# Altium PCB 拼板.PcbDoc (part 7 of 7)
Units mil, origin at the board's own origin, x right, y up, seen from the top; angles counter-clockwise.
Board outline 3630.03 x 5330.03 mil, 2 copper layers (Top Layer, Bottom Layer); 416 components, 35 nets, 1936 pads, 800 vias.
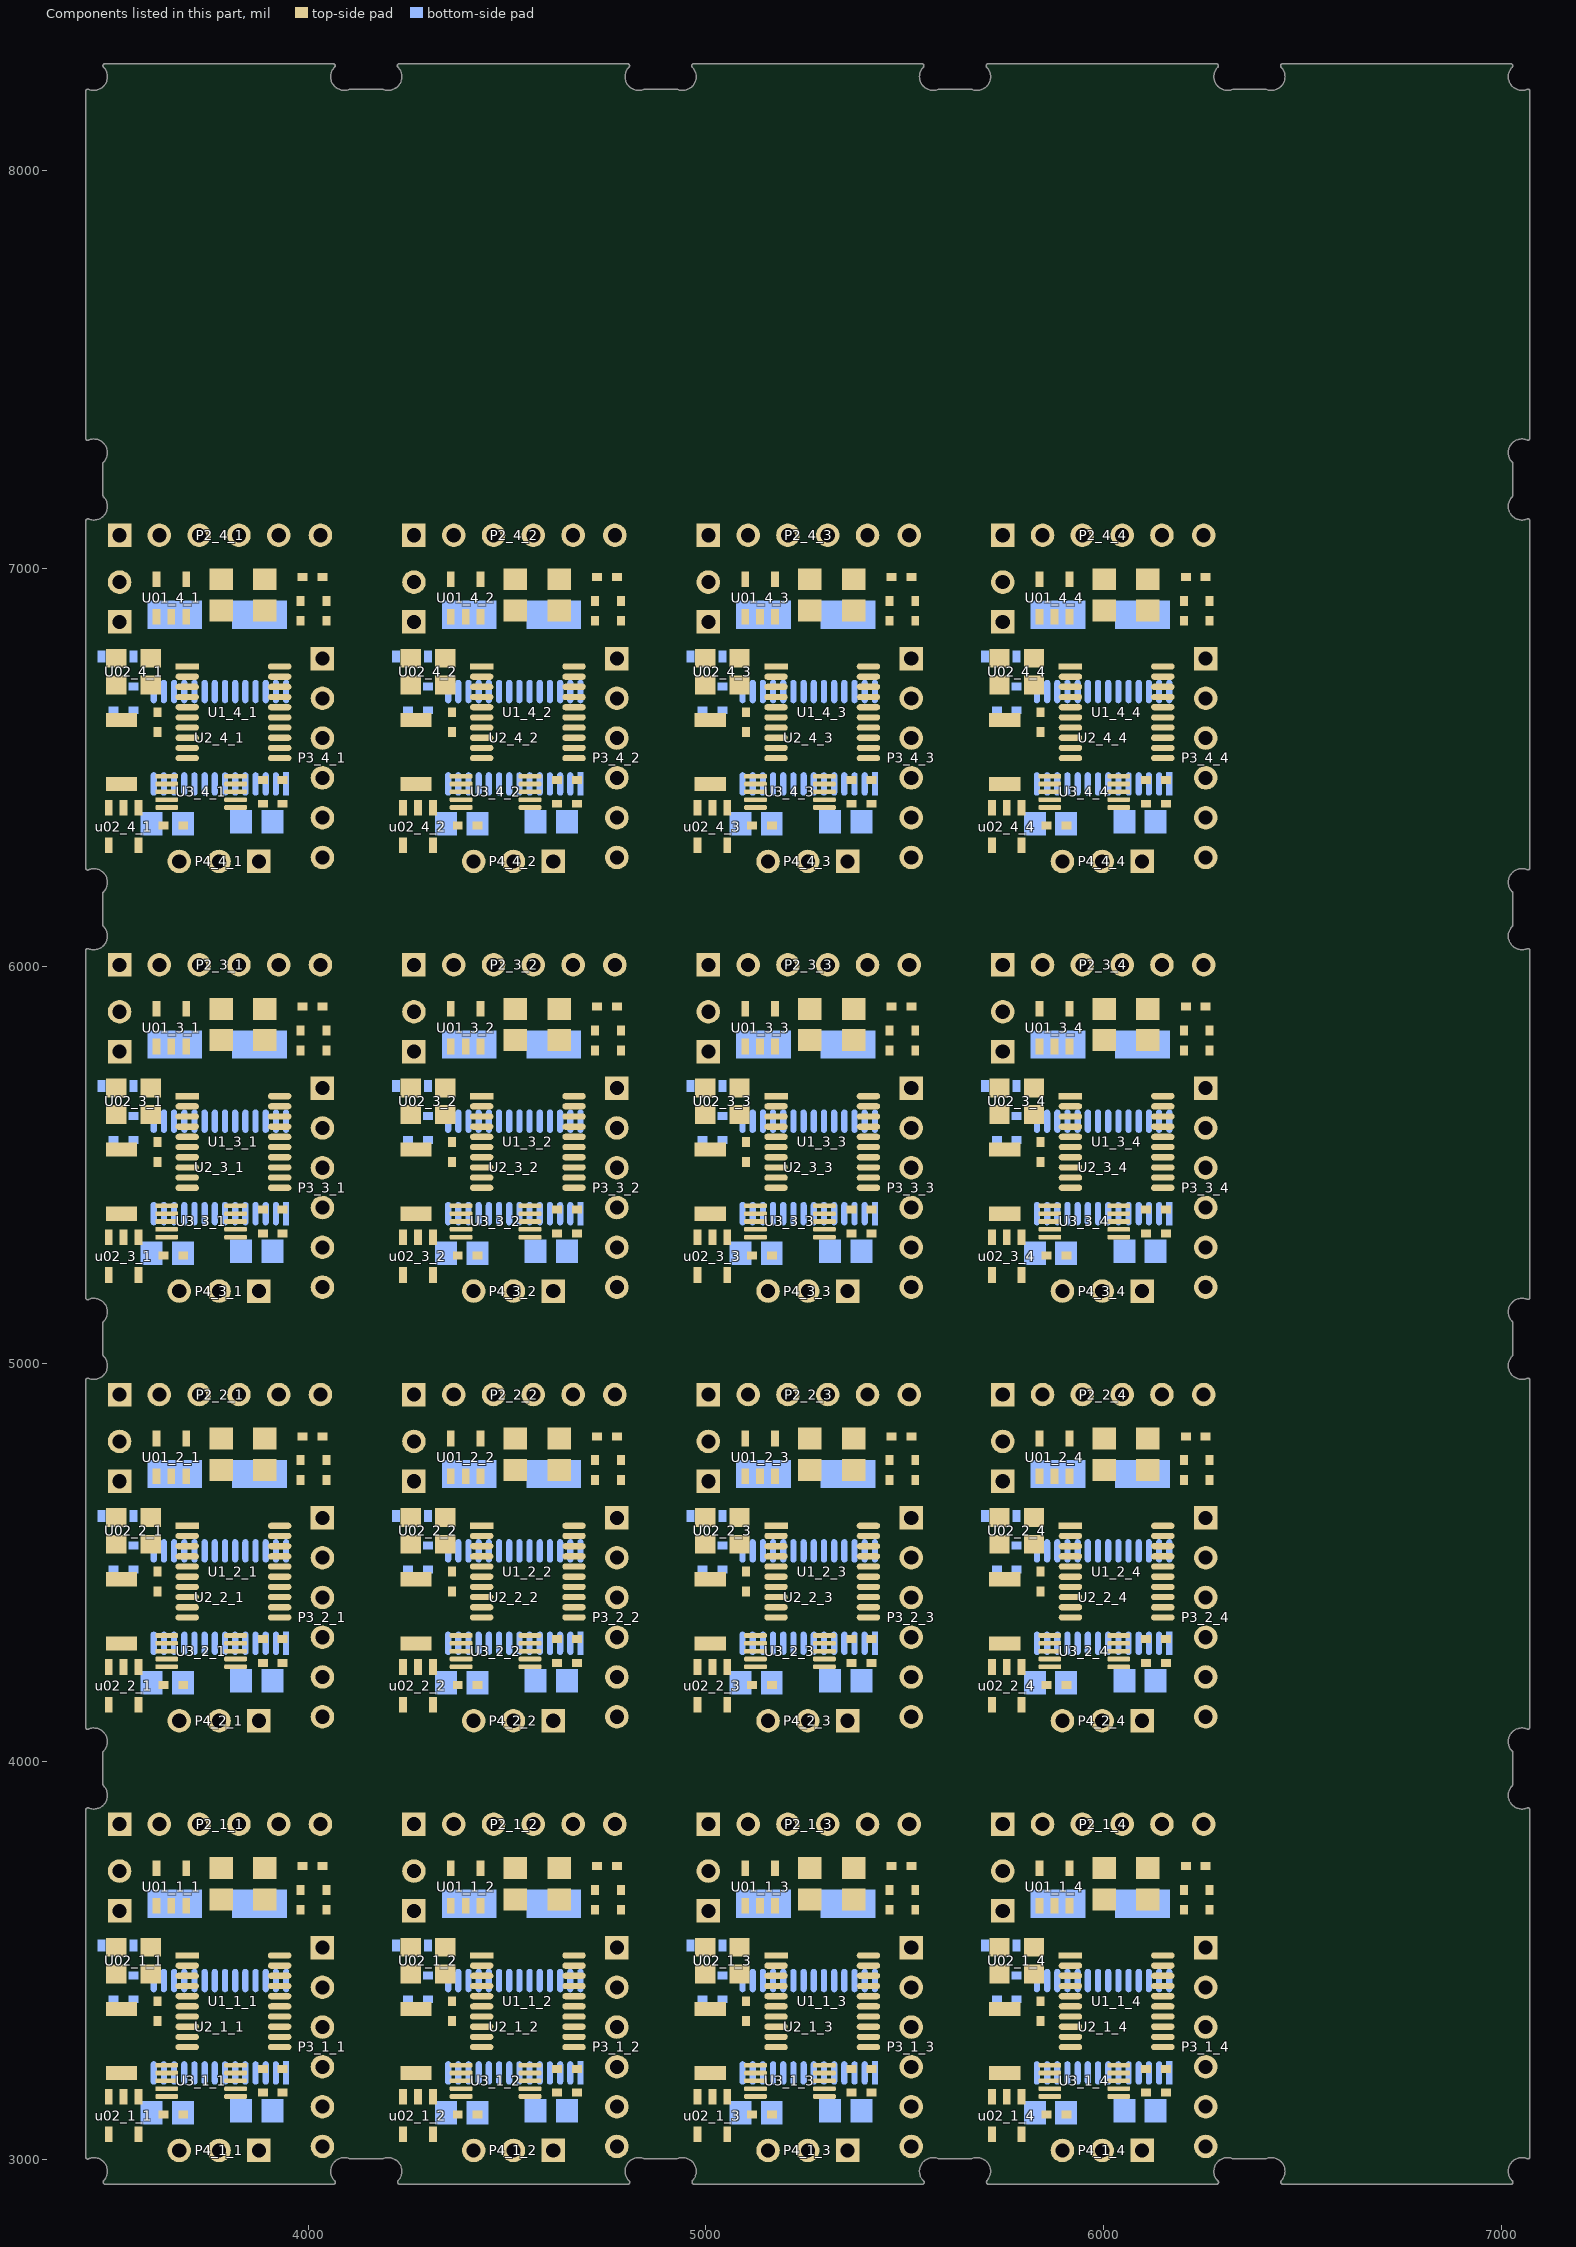
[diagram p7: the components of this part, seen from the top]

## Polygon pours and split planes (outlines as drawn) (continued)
no net on Bottom Layer "Top Layer-No Net1" (solid, pour order 43): 4929.77,3003.01 cw(c4926.07,3006.39) 4921.05,3006.39 4921.05,3879.08 cw(c4926.07,3879.08) 4927.98,3883.71 ccw(c4941.11,3915.46) 4975.46,3915.46 ccw(c4941.11,3915.46) 4965.67,3939.48 ccw(c4941.11,3915.46) 4965.64,3939.51 4965.67,3939.48 cw(c4969.22,3943.02) 4964.21,3943.02 cw(c4969.22,3943.02) 4969.25,3948.04 5542.91,3948.04 cw(c5542.91,3943.02) 5547.93,3943.02 cw(c5542.91,3943.02) 5546.47,3939.49 cw(c5571.03,3915.46) 5546.49,3939.51 5546.47,3939.49 ccw(c5571.03,3915.46) 5584.15,3883.71 cw(c5586.07,3879.08) 5591.08,3879.08 cw(c5586.07,3879.08) 5591.08,3879.08 5591.08,3006.97 cw(c5586.07,3006.97) 5584.15,3002.33 ccw(c5571.03,2970.58) 5545.44,2947.65 cw(c5543.51,2943.02) 5548.53,2943.02 cw(c5543.51,2943.02) 5543.51,2938.01 5537.29,2938.01 cw(c5537.29,2943.02) 5537.29,2938.01 ccw(c5537.29,2943.02) 5537.32,2938.01 5537.29,2938.01 4970.1,2938.01 cw(c4970.1,2943.02) 4965.11,2943.49 cw(c4970.1,2943.95) 4966.41,2947.34 ccw(c4941.11,2970.58) 4975.46,2970.58 ccw(c4941.11,2970.58)
no net on Bottom Layer "Top Layer-No Net1" (solid, pour order 37): 4189.77,5163.01 cw(c4186.07,5166.39) 4181.05,5166.39 4181.05,6039.08 cw(c4186.07,6039.08) 4187.98,6043.71 ccw(c4201.11,6075.46) 4235.46,6075.46 ccw(c4201.11,6075.46) 4225.67,6099.48 ccw(c4201.11,6075.46) 4225.64,6099.51 4225.67,6099.48 cw(c4229.22,6103.02) 4224.21,6103.02 cw(c4229.22,6103.02) 4229.25,6108.04 4802.91,6108.04 cw(c4802.91,6103.02) 4807.93,6103.02 cw(c4802.91,6103.02) 4806.47,6099.49 cw(c4831.03,6075.46) 4806.49,6099.51 4806.47,6099.49 ccw(c4831.03,6075.46) 4844.15,6043.71 cw(c4846.07,6039.08) 4851.08,6039.08 cw(c4846.07,6039.08) 4851.08,6039.08 4851.08,5166.97 cw(c4846.07,5166.97) 4844.15,5162.33 ccw(c4831.03,5130.58) 4805.44,5107.65 cw(c4803.51,5103.02) 4808.53,5103.02 cw(c4803.51,5103.02) 4803.51,5098.01 4797.29,5098.01 cw(c4797.29,5103.02) 4797.29,5098.01 ccw(c4797.29,5103.02) 4797.32,5098.01 4797.29,5098.01 4230.1,5098.01 cw(c4230.1,5103.02) 4225.11,5103.49 cw(c4230.1,5103.95) 4226.41,5107.34 ccw(c4201.11,5130.58) 4235.46,5130.58 ccw(c4201.11,5130.58)
no net on Bottom Layer "Top Layer-No Net1" (solid, pour order 35): 4189.77,4083.01 cw(c4186.07,4086.39) 4181.05,4086.39 4181.05,4959.08 cw(c4186.07,4959.08) 4187.98,4963.71 ccw(c4201.11,4995.46) 4235.46,4995.46 ccw(c4201.11,4995.46) 4225.67,5019.48 ccw(c4201.11,4995.46) 4225.64,5019.51 4225.67,5019.48 cw(c4229.22,5023.02) 4224.21,5023.02 cw(c4229.22,5023.02) 4229.25,5028.04 4802.91,5028.04 cw(c4802.91,5023.02) 4807.93,5023.02 cw(c4802.91,5023.02) 4806.47,5019.49 cw(c4831.03,4995.46) 4806.49,5019.51 4806.47,5019.49 ccw(c4831.03,4995.46) 4844.15,4963.71 cw(c4846.07,4959.08) 4851.08,4959.08 cw(c4846.07,4959.08) 4851.08,4959.08 4851.08,4086.97 cw(c4846.07,4086.97) 4844.15,4082.33 ccw(c4831.03,4050.58) 4805.44,4027.65 cw(c4803.51,4023.02) 4808.53,4023.02 cw(c4803.51,4023.02) 4803.51,4018.01 4797.29,4018.01 cw(c4797.29,4023.02) 4797.29,4018.01 ccw(c4797.29,4023.02) 4797.32,4018.01 4797.29,4018.01 4230.1,4018.01 cw(c4230.1,4023.02) 4225.11,4023.49 cw(c4230.1,4023.95) 4226.41,4027.34 ccw(c4201.11,4050.58) 4235.46,4050.58 ccw(c4201.11,4050.58)
no net on Bottom Layer "Top Layer-No Net1" (solid, pour order 33): 4189.77,3003.01 cw(c4186.07,3006.39) 4181.05,3006.39 4181.05,3879.08 cw(c4186.07,3879.08) 4187.98,3883.71 ccw(c4201.11,3915.46) 4235.46,3915.46 ccw(c4201.11,3915.46) 4225.67,3939.48 ccw(c4201.11,3915.46) 4225.64,3939.51 4225.67,3939.48 cw(c4229.22,3943.02) 4224.21,3943.02 cw(c4229.22,3943.02) 4229.25,3948.04 4802.91,3948.04 cw(c4802.91,3943.02) 4807.93,3943.02 cw(c4802.91,3943.02) 4806.47,3939.49 cw(c4831.03,3915.46) 4806.49,3939.51 4806.47,3939.49 ccw(c4831.03,3915.46) 4844.15,3883.71 cw(c4846.07,3879.08) 4851.08,3879.08 cw(c4846.07,3879.08) 4851.08,3879.08 4851.08,3006.97 cw(c4846.07,3006.97) 4844.15,3002.33 ccw(c4831.03,2970.58) 4805.44,2947.65 cw(c4803.51,2943.02) 4808.53,2943.02 cw(c4803.51,2943.02) 4803.51,2938.01 4797.29,2938.01 cw(c4797.29,2943.02) 4797.29,2938.01 ccw(c4797.29,2943.02) 4797.32,2938.01 4797.29,2938.01 4230.1,2938.01 cw(c4230.1,2943.02) 4225.11,2943.49 cw(c4230.1,2943.95) 4226.41,2947.34 ccw(c4201.11,2970.58) 4235.46,2970.58 ccw(c4201.11,2970.58)
no net on Bottom Layer "Top Layer-No Net1" (solid, pour order 27): 3449.77,5163.01 cw(c3446.07,5166.39) 3441.05,5166.39 3441.05,6039.08 cw(c3446.07,6039.08) 3447.98,6043.71 ccw(c3461.11,6075.46) 3495.46,6075.46 ccw(c3461.11,6075.46) 3485.67,6099.48 ccw(c3461.11,6075.46) 3485.64,6099.51 3485.67,6099.48 cw(c3489.22,6103.02) 3484.21,6103.02 cw(c3489.22,6103.02) 3489.25,6108.04 4062.91,6108.04 cw(c4062.91,6103.02) 4067.93,6103.02 cw(c4062.91,6103.02) 4066.47,6099.49 cw(c4091.03,6075.46) 4066.49,6099.51 4066.47,6099.49 ccw(c4091.03,6075.46) 4104.15,6043.71 cw(c4106.07,6039.08) 4111.08,6039.08 cw(c4106.07,6039.08) 4111.08,6039.08 4111.08,5166.97 cw(c4106.07,5166.97) 4104.15,5162.33 ccw(c4091.03,5130.58) 4065.44,5107.65 cw(c4063.51,5103.02) 4068.53,5103.02 cw(c4063.51,5103.02) 4063.51,5098.01 4057.29,5098.01 cw(c4057.29,5103.02) 4057.29,5098.01 ccw(c4057.29,5103.02) 4057.32,5098.01 4057.29,5098.01 3490.1,5098.01 cw(c3490.1,5103.02) 3485.11,5103.49 cw(c3490.1,5103.95) 3486.41,5107.34 ccw(c3461.11,5130.58) 3495.46,5130.58 ccw(c3461.11,5130.58)
no net on Bottom Layer "Top Layer-No Net1" (solid, pour order 25): 3449.77,4083.01 cw(c3446.07,4086.39) 3441.05,4086.39 3441.05,4959.08 cw(c3446.07,4959.08) 3447.98,4963.71 ccw(c3461.11,4995.46) 3495.46,4995.46 ccw(c3461.11,4995.46) 3485.67,5019.48 ccw(c3461.11,4995.46) 3485.64,5019.51 3485.67,5019.48 cw(c3489.22,5023.02) 3484.21,5023.02 cw(c3489.22,5023.02) 3489.25,5028.04 4062.91,5028.04 cw(c4062.91,5023.02) 4067.93,5023.02 cw(c4062.91,5023.02) 4066.47,5019.49 cw(c4091.03,4995.46) 4066.49,5019.51 4066.47,5019.49 ccw(c4091.03,4995.46) 4104.15,4963.71 cw(c4106.07,4959.08) 4111.08,4959.08 cw(c4106.07,4959.08) 4111.08,4959.08 4111.08,4086.97 cw(c4106.07,4086.97) 4104.15,4082.33 ccw(c4091.03,4050.58) 4065.44,4027.65 cw(c4063.51,4023.02) 4068.53,4023.02 cw(c4063.51,4023.02) 4063.51,4018.01 4057.29,4018.01 cw(c4057.29,4023.02) 4057.29,4018.01 ccw(c4057.29,4023.02) 4057.32,4018.01 4057.29,4018.01 3490.1,4018.01 cw(c3490.1,4023.02) 3485.11,4023.49 cw(c3490.1,4023.95) 3486.41,4027.34 ccw(c3461.11,4050.58) 3495.46,4050.58 ccw(c3461.11,4050.58)
no net on Bottom Layer "Top Layer-No Net1" (solid, pour order 23): 3449.77,3003.01 cw(c3446.07,3006.39) 3441.05,3006.39 3441.05,3879.08 cw(c3446.07,3879.08) 3447.98,3883.71 ccw(c3461.11,3915.46) 3495.46,3915.46 ccw(c3461.11,3915.46) 3485.67,3939.48 ccw(c3461.11,3915.46) 3485.64,3939.51 3485.67,3939.48 cw(c3489.22,3943.02) 3484.21,3943.02 cw(c3489.22,3943.02) 3489.25,3948.04 4062.91,3948.04 cw(c4062.91,3943.02) 4067.93,3943.02 cw(c4062.91,3943.02) 4066.47,3939.49 cw(c4091.03,3915.46) 4066.49,3939.51 4066.47,3939.49 ccw(c4091.03,3915.46) 4104.15,3883.71 cw(c4106.07,3879.08) 4111.08,3879.08 cw(c4106.07,3879.08) 4111.08,3879.08 4111.08,3006.97 cw(c4106.07,3006.97) 4104.15,3002.33 ccw(c4091.03,2970.58) 4065.44,2947.65 cw(c4063.51,2943.02) 4068.53,2943.02 cw(c4063.51,2943.02) 4063.51,2938.01 4057.29,2938.01 cw(c4057.29,2943.02) 4057.29,2938.01 ccw(c4057.29,2943.02) 4057.32,2938.01 4057.29,2938.01 3490.1,2938.01 cw(c3490.1,2943.02) 3485.11,2943.49 cw(c3490.1,2943.95) 3486.41,2947.34 ccw(c3461.11,2970.58) 3495.46,2970.58 ccw(c3461.11,2970.58)
no net on Bottom Layer "Top Layer-No Net1" (solid, pour order 47): 4929.77,5163.01 cw(c4926.07,5166.39) 4921.05,5166.39 4921.05,6039.08 cw(c4926.07,6039.08) 4927.98,6043.71 ccw(c4941.11,6075.46) 4975.46,6075.46 ccw(c4941.11,6075.46) 4965.67,6099.48 ccw(c4941.11,6075.46) 4965.64,6099.51 4965.67,6099.48 cw(c4969.22,6103.02) 4964.21,6103.02 cw(c4969.22,6103.02) 4969.25,6108.04 5542.91,6108.04 cw(c5542.91,6103.02) 5547.93,6103.02 cw(c5542.91,6103.02) 5546.47,6099.49 cw(c5571.03,6075.46) 5546.49,6099.51 5546.47,6099.49 ccw(c5571.03,6075.46) 5584.15,6043.71 cw(c5586.07,6039.08) 5591.08,6039.08 cw(c5586.07,6039.08) 5591.08,6039.08 5591.08,5166.97 cw(c5586.07,5166.97) 5584.15,5162.33 ccw(c5571.03,5130.58) 5545.44,5107.65 cw(c5543.51,5103.02) 5548.53,5103.02 cw(c5543.51,5103.02) 5543.51,5098.01 5537.29,5098.01 cw(c5537.29,5103.02) 5537.29,5098.01 ccw(c5537.29,5103.02) 5537.32,5098.01 5537.29,5098.01 4970.1,5098.01 cw(c4970.1,5103.02) 4965.11,5103.49 cw(c4970.1,5103.95) 4966.41,5107.34 ccw(c4941.11,5130.58) 4975.46,5130.58 ccw(c4941.11,5130.58)
no net on Bottom Layer "Top Layer-No Net1" (solid, pour order 59): 5669.77,6243.01 cw(c5666.07,6246.39) 5661.05,6246.39 5661.05,7119.08 cw(c5666.07,7119.08) 5667.98,7123.71 ccw(c5681.11,7155.46) 5715.46,7155.46 ccw(c5681.11,7155.46) 5705.67,7179.48 ccw(c5681.11,7155.46) 5705.64,7179.51 5705.67,7179.48 cw(c5709.22,7183.02) 5704.21,7183.02 cw(c5709.22,7183.02) 5709.25,7188.04 6282.91,7188.04 cw(c6282.91,7183.02) 6287.93,7183.02 cw(c6282.91,7183.02) 6286.47,7179.49 cw(c6311.03,7155.46) 6286.49,7179.51 6286.47,7179.49 ccw(c6311.03,7155.46) 6324.15,7123.71 cw(c6326.07,7119.08) 6331.08,7119.08 cw(c6326.07,7119.08) 6331.08,7119.08 6331.08,6246.97 cw(c6326.07,6246.97) 6324.15,6242.33 ccw(c6311.03,6210.58) 6285.44,6187.65 cw(c6283.51,6183.02) 6288.53,6183.02 cw(c6283.51,6183.02) 6283.51,6178.01 6277.29,6178.01 cw(c6277.29,6183.02) 6277.29,6178.01 ccw(c6277.29,6183.02) 6277.32,6178.01 6277.29,6178.01 5710.1,6178.01 cw(c5710.1,6183.02) 5705.11,6183.49 cw(c5710.1,6183.95) 5706.41,6187.34 ccw(c5681.11,6210.58) 5715.46,6210.58 ccw(c5681.11,6210.58)
no net on Bottom Layer "Top Layer-No Net1" (solid, pour order 49): 4929.77,6243.01 cw(c4926.07,6246.39) 4921.05,6246.39 4921.05,7119.08 cw(c4926.07,7119.08) 4927.98,7123.71 ccw(c4941.11,7155.46) 4975.46,7155.46 ccw(c4941.11,7155.46) 4965.67,7179.48 ccw(c4941.11,7155.46) 4965.64,7179.51 4965.67,7179.48 cw(c4969.22,7183.02) 4964.21,7183.02 cw(c4969.22,7183.02) 4969.25,7188.04 5542.91,7188.04 cw(c5542.91,7183.02) 5547.93,7183.02 cw(c5542.91,7183.02) 5546.47,7179.49 cw(c5571.03,7155.46) 5546.49,7179.51 5546.47,7179.49 ccw(c5571.03,7155.46) 5584.15,7123.71 cw(c5586.07,7119.08) 5591.08,7119.08 cw(c5586.07,7119.08) 5591.08,7119.08 5591.08,6246.97 cw(c5586.07,6246.97) 5584.15,6242.33 ccw(c5571.03,6210.58) 5545.44,6187.65 cw(c5543.51,6183.02) 5548.53,6183.02 cw(c5543.51,6183.02) 5543.51,6178.01 5537.29,6178.01 cw(c5537.29,6183.02) 5537.29,6178.01 ccw(c5537.29,6183.02) 5537.32,6178.01 5537.29,6178.01 4970.1,6178.01 cw(c4970.1,6183.02) 4965.11,6183.49 cw(c4970.1,6183.95) 4966.41,6187.34 ccw(c4941.11,6210.58) 4975.46,6210.58 ccw(c4941.11,6210.58)
no net on Bottom Layer "Top Layer-No Net1" (solid, pour order 39): 4189.77,6243.01 cw(c4186.07,6246.39) 4181.05,6246.39 4181.05,7119.08 cw(c4186.07,7119.08) 4187.98,7123.71 ccw(c4201.11,7155.46) 4235.46,7155.46 ccw(c4201.11,7155.46) 4225.67,7179.48 ccw(c4201.11,7155.46) 4225.64,7179.51 4225.67,7179.48 cw(c4229.22,7183.02) 4224.21,7183.02 cw(c4229.22,7183.02) 4229.25,7188.04 4802.91,7188.04 cw(c4802.91,7183.02) 4807.93,7183.02 cw(c4802.91,7183.02) 4806.47,7179.49 cw(c4831.03,7155.46) 4806.49,7179.51 4806.47,7179.49 ccw(c4831.03,7155.46) 4844.15,7123.71 cw(c4846.07,7119.08) 4851.08,7119.08 cw(c4846.07,7119.08) 4851.08,7119.08 4851.08,6246.97 cw(c4846.07,6246.97) 4844.15,6242.33 ccw(c4831.03,6210.58) 4805.44,6187.65 cw(c4803.51,6183.02) 4808.53,6183.02 cw(c4803.51,6183.02) 4803.51,6178.01 4797.29,6178.01 cw(c4797.29,6183.02) 4797.29,6178.01 ccw(c4797.29,6183.02) 4797.32,6178.01 4797.29,6178.01 4230.1,6178.01 cw(c4230.1,6183.02) 4225.11,6183.49 cw(c4230.1,6183.95) 4226.41,6187.34 ccw(c4201.11,6210.58) 4235.46,6210.58 ccw(c4201.11,6210.58)
no net on Bottom Layer "Top Layer-No Net1" (solid, pour order 29): 3449.77,6243.01 cw(c3446.07,6246.39) 3441.05,6246.39 3441.05,7119.08 cw(c3446.07,7119.08) 3447.98,7123.71 ccw(c3461.11,7155.46) 3495.46,7155.46 ccw(c3461.11,7155.46) 3485.67,7179.48 ccw(c3461.11,7155.46) 3485.64,7179.51 3485.67,7179.48 cw(c3489.22,7183.02) 3484.21,7183.02 cw(c3489.22,7183.02) 3489.25,7188.04 4062.91,7188.04 cw(c4062.91,7183.02) 4067.93,7183.02 cw(c4062.91,7183.02) 4066.47,7179.49 cw(c4091.03,7155.46) 4066.49,7179.51 4066.47,7179.49 ccw(c4091.03,7155.46) 4104.15,7123.71 cw(c4106.07,7119.08) 4111.08,7119.08 cw(c4106.07,7119.08) 4111.08,7119.08 4111.08,6246.97 cw(c4106.07,6246.97) 4104.15,6242.33 ccw(c4091.03,6210.58) 4065.44,6187.65 cw(c4063.51,6183.02) 4068.53,6183.02 cw(c4063.51,6183.02) 4063.51,6178.01 4057.29,6178.01 cw(c4057.29,6183.02) 4057.29,6178.01 ccw(c4057.29,6183.02) 4057.32,6178.01 4057.29,6178.01 3490.1,6178.01 cw(c3490.1,6183.02) 3485.11,6183.49 cw(c3490.1,6183.95) 3486.41,6187.34 ccw(c3461.11,6210.58) 3495.46,6210.58 ccw(c3461.11,6210.58)
no net on Bottom Layer "Top Layer-No Net1" (solid, pour order 57): 5669.77,5163.01 cw(c5666.07,5166.39) 5661.05,5166.39 5661.05,6039.08 cw(c5666.07,6039.08) 5667.98,6043.71 ccw(c5681.11,6075.46) 5715.46,6075.46 ccw(c5681.11,6075.46) 5705.67,6099.48 ccw(c5681.11,6075.46) 5705.64,6099.51 5705.67,6099.48 cw(c5709.22,6103.02) 5704.21,6103.02 cw(c5709.22,6103.02) 5709.25,6108.04 6282.91,6108.04 cw(c6282.91,6103.02) 6287.93,6103.02 cw(c6282.91,6103.02) 6286.47,6099.49 cw(c6311.03,6075.46) 6286.49,6099.51 6286.47,6099.49 ccw(c6311.03,6075.46) 6324.15,6043.71 cw(c6326.07,6039.08) 6331.08,6039.08 cw(c6326.07,6039.08) 6331.08,6039.08 6331.08,5166.97 cw(c6326.07,5166.97) 6324.15,5162.33 ccw(c6311.03,5130.58) 6285.44,5107.65 cw(c6283.51,5103.02) 6288.53,5103.02 cw(c6283.51,5103.02) 6283.51,5098.01 6277.29,5098.01 cw(c6277.29,5103.02) 6277.29,5098.01 ccw(c6277.29,5103.02) 6277.32,5098.01 6277.29,5098.01 5710.1,5098.01 cw(c5710.1,5103.02) 5705.11,5103.49 cw(c5710.1,5103.95) 5706.41,5107.34 ccw(c5681.11,5130.58) 5715.46,5130.58 ccw(c5681.11,5130.58)
no net on Bottom Layer "Top Layer-No Net1" (solid, pour order 53): 5669.77,3003.01 cw(c5666.07,3006.39) 5661.05,3006.39 5661.05,3879.08 cw(c5666.07,3879.08) 5667.98,3883.71 ccw(c5681.11,3915.46) 5715.46,3915.46 ccw(c5681.11,3915.46) 5705.67,3939.48 ccw(c5681.11,3915.46) 5705.64,3939.51 5705.67,3939.48 cw(c5709.22,3943.02) 5704.21,3943.02 cw(c5709.22,3943.02) 5709.25,3948.04 6282.91,3948.04 cw(c6282.91,3943.02) 6287.93,3943.02 cw(c6282.91,3943.02) 6286.47,3939.49 cw(c6311.03,3915.46) 6286.49,3939.51 6286.47,3939.49 ccw(c6311.03,3915.46) 6324.15,3883.71 cw(c6326.07,3879.08) 6331.08,3879.08 cw(c6326.07,3879.08) 6331.08,3879.08 6331.08,3006.97 cw(c6326.07,3006.97) 6324.15,3002.33 ccw(c6311.03,2970.58) 6285.44,2947.65 cw(c6283.51,2943.02) 6288.53,2943.02 cw(c6283.51,2943.02) 6283.51,2938.01 6277.29,2938.01 cw(c6277.29,2943.02) 6277.29,2938.01 ccw(c6277.29,2943.02) 6277.32,2938.01 6277.29,2938.01 5710.1,2938.01 cw(c5710.1,2943.02) 5705.11,2943.49 cw(c5710.1,2943.95) 5706.41,2947.34 ccw(c5681.11,2970.58) 5715.46,2970.58 ccw(c5681.11,2970.58)
no net on Bottom Layer "Top Layer-No Net1" (solid, pour order 55): 5669.77,4083.01 cw(c5666.07,4086.39) 5661.05,4086.39 5661.05,4959.08 cw(c5666.07,4959.08) 5667.98,4963.71 ccw(c5681.11,4995.46) 5715.46,4995.46 ccw(c5681.11,4995.46) 5705.67,5019.48 ccw(c5681.11,4995.46) 5705.64,5019.51 5705.67,5019.48 cw(c5709.22,5023.02) 5704.21,5023.02 cw(c5709.22,5023.02) 5709.25,5028.04 6282.91,5028.04 cw(c6282.91,5023.02) 6287.93,5023.02 cw(c6282.91,5023.02) 6286.47,5019.49 cw(c6311.03,4995.46) 6286.49,5019.51 6286.47,5019.49 ccw(c6311.03,4995.46) 6324.15,4963.71 cw(c6326.07,4959.08) 6331.08,4959.08 cw(c6326.07,4959.08) 6331.08,4959.08 6331.08,4086.97 cw(c6326.07,4086.97) 6324.15,4082.33 ccw(c6311.03,4050.58) 6285.44,4027.65 cw(c6283.51,4023.02) 6288.53,4023.02 cw(c6283.51,4023.02) 6283.51,4018.01 6277.29,4018.01 cw(c6277.29,4023.02) 6277.29,4018.01 ccw(c6277.29,4023.02) 6277.32,4018.01 6277.29,4018.01 5710.1,4018.01 cw(c5710.1,4023.02) 5705.11,4023.49 cw(c5710.1,4023.95) 5706.41,4027.34 ccw(c5681.11,4050.58) 5715.46,4050.58 ccw(c5681.11,4050.58)

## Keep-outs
Keep-Out Layer:
  lines w10: 3446.07,3006.39 3446.07,3879.08 ccw(c3461.11,3915.46) 3489.22,3943.02 3489.07,4023.02 ; 3446.07,3006.97 cw(c3461.11,2970.58) 3490.1,2943.95 ; 3446.07,4086.39 3446.07,4959.08 ccw(c3461.11,4995.46) 3489.22,5023.02 3489.07,5103.02 ; 3446.07,4086.97 cw(c3461.11,4050.58) 3490.1,4023.95 ; 3446.07,5166.39 3446.07,6039.08 ccw(c3461.11,6075.46) 3489.22,6103.02 3489.07,6183.02 ; 3446.07,5166.97 cw(c3461.11,5130.58) 3490.1,5103.95 ; 3446.07,6246.39 3446.07,7119.08 ccw(c3461.11,7155.46) 3489.22,7183.02 4062.91,7183.02 ccw(c4091.03,7155.46) 4106.07,7119.08 4186.07,7119.08 ccw(c4201.11,7155.46) 4229.22,7183.02 4802.91,7183.02 ccw(c4831.03,7155.46) 4846.07,7119.08 4926.07,7119.08 ccw(c4941.11,7155.46) 4969.22,7183.02 5542.91,7183.02 ccw(c5571.03,7155.46) 5586.07,7119.08 5666.07,7119.08 ccw(c5681.11,7155.46) 5709.22,7183.02 6282.91,7183.02 ccw(c6311.03,7155.46) 6326.07,7119.08 6326.07,6250 ; 3446.07,6246.97 cw(c3461.11,6210.58) 3490.1,6183.95 ; 3490.1,2943.02 4057.29,2943.02 ; 4062.91,2943.02 cw(c4091.03,2970.58) 4106.07,3006.97 4186.07,3007.12 ; 4063.51,2943.02 4057.29,2943.02 ; 4063.51,4023.02 4057.29,4023.02 ; 4063.51,5103.02 4057.29,5103.02 ; 4063.51,6183.02 4057.29,6183.02 ; 4186.07,3006.97 cw(c4201.11,2970.58) 4230.1,2943.95 ; 4186.07,4086.97 cw(c4201.11,4050.58) 4230.1,4023.95 ; 4186.07,4087.12 4106.07,4086.97 ccw(c4091.03,4050.58) 4062.91,4023.02 4062.91,3943.02 ccw(c4091.03,3915.46) 4106.07,3879.08 4186.07,3879.08 ccw(c4201.11,3915.46) 4229.22,3943.02 4229.07,4023.02 ; 4186.07,5166.97 cw(c4201.11,5130.58) 4230.1,5103.95 ; 4186.07,5167.12 4106.07,5166.97 ccw(c4091.03,5130.58) 4062.91,5103.02 4062.91,5023.02 ccw(c4091.03,4995.46) 4106.07,4959.08 4186.07,4959.08 ccw(c4201.11,4995.46) 4229.22,5023.02 4229.07,5103.02 ; 4186.07,6246.97 cw(c4201.11,6210.58) 4230.1,6183.95 ; 4186.07,6247.12 4106.07,6246.97 ccw(c4091.03,6210.58) 4062.91,6183.02 4062.91,6103.02 ccw(c4091.03,6075.46) 4106.07,6039.08 4186.07,6039.08 ccw(c4201.11,6075.46) 4229.22,6103.02 4229.07,6183.02 ; 4230.1,2943.02 4797.29,2943.02 ; 4802.91,2943.02 cw(c4831.03,2970.58) 4846.07,3006.97 4926.07,3007.12 ; 4803.51,2943.02 4797.29,2943.02 ; 4803.51,4023.02 4797.29,4023.02 ; 4803.51,5103.02 4797.29,5103.02 ; 4803.51,6183.02 4797.29,6183.02 ; 4926.07,3006.97 cw(c4941.11,2970.58) 4970.1,2943.95 ; 4926.07,4086.97 cw(c4941.11,4050.58) 4970.1,4023.95 ; 4926.07,4087.12 4846.07,4086.97 ccw(c4831.03,4050.58) 4802.91,4023.02 4802.91,3943.02 ccw(c4831.03,3915.46) 4846.07,3879.08 4926.07,3879.08 ccw(c4941.11,3915.46) 4969.22,3943.02 4969.07,4023.02 ; 4926.07,5166.97 cw(c4941.11,5130.58) 4970.1,5103.95 ; 4926.07,5167.12 4846.07,5166.97 ccw(c4831.03,5130.58) 4802.91,5103.02 4802.91,5023.02 ccw(c4831.03,4995.46) 4846.07,4959.08 4926.07,4959.08 ccw(c4941.11,4995.46) 4969.22,5023.02 4969.07,5103.02 ; 4926.07,6246.97 cw(c4941.11,6210.58) 4970.1,6183.95 ; 4926.07,6247.12 4846.07,6246.97 ccw(c4831.03,6210.58) 4802.91,6183.02 4802.91,6103.02 ccw(c4831.03,6075.46) 4846.07,6039.08 4926.07,6039.08 ccw(c4941.11,6075.46) 4969.22,6103.02 4969.07,6183.02 ; 4970.1,2943.02 5537.29,2943.02 ; 5542.91,2943.02 cw(c5571.03,2970.58) 5586.07,3006.97 5666.07,3007.12 ; 5543.51,2943.02 5537.29,2943.02 ; 5543.51,4023.02 5537.29,4023.02 ; 5543.51,5103.02 5537.29,5103.02 ; 5543.51,6183.02 5537.29,6183.02 ; 5666.07,3006.97 cw(c5681.11,2970.58) 5710.1,2943.95 ; 5666.07,4086.97 cw(c5681.11,4050.58) 5710.1,4023.95 ; 5666.07,4087.12 5586.07,4086.97 ccw(c5571.03,4050.58) 5542.91,4023.02 5542.91,3943.02 ccw(c5571.03,3915.46) 5586.07,3879.08 5666.07,3879.08 ccw(c5681.11,3915.46) 5709.22,3943.02 5709.07,4023.02 ; 5666.07,5166.97 cw(c5681.11,5130.58) 5710.1,5103.95 ; 5666.07,5167.12 5586.07,5166.97 ccw(c5571.03,5130.58) 5542.91,5103.02 5542.91,5023.02 ccw(c5571.03,4995.46) 5586.07,4959.08 5666.07,4959.08 ccw(c5681.11,4995.46) 5709.22,5023.02 5709.07,5103.02 ; 5666.07,6246.97 cw(c5681.11,6210.58) 5710.1,6183.95 ; 5666.07,6247.12 5586.07,6246.97 ccw(c5571.03,6210.58) 5542.91,6183.02 5542.91,6103.02 ccw(c5571.03,6075.46) 5586.07,6039.08 5666.07,6039.08 ccw(c5681.11,6075.46) 5709.22,6103.02 5709.07,6183.02 ; 5710.1,2943.02 6277.29,2943.02 ; 6282.91,2943.02 cw(c6311.03,2970.58) 6326.07,3006.97 6326.07,3879.08 cw(c6311.03,3915.46) 6282.91,3943.02 6282.91,4023.02 cw(c6311.03,4050.58) 6326.07,4086.97 6326.07,4959.08 cw(c6311.03,4995.46) 6282.91,5023.02 6282.91,5103.02 cw(c6311.03,5130.58) 6326.07,5166.97 ; 6283.51,2943.02 6277.29,2943.02 ; 6283.51,4023.02 6277.29,4023.02 ; 6283.51,5103.02 6277.29,5103.02 ; 6283.51,6183.02 6277.29,6183.02 ; 6326.07,5162.8 6326.07,6039.08 cw(c6311.03,6075.46) 6282.91,6103.02 6282.91,6183.02 cw(c6311.03,6210.58) 6326.07,6246.97 ; 4057.29,2943.02 4057.29,2943.02 ; 4057.29,4023.02 4057.29,4023.02 ; 4057.29,5103.02 4057.29,5103.02 ; 4057.29,6183.02 4057.29,6183.02 ; 4797.29,2943.02 4797.29,2943.02 ; 4797.29,4023.02 4797.29,4023.02 ; 4797.29,5103.02 4797.29,5103.02 ; 4797.29,6183.02 4797.29,6183.02 ; 5537.29,2943.02 5537.29,2943.02 ; 5537.29,4023.02 5537.29,4023.02 ; 5537.29,5103.02 5537.29,5103.02 ; 5537.29,6183.02 5537.29,6183.02 ; 6277.29,2943.02 6277.29,2943.02 ; 6277.29,4023.02 6277.29,4023.02 ; 6277.29,5103.02 6277.29,5103.02 ; 6277.29,6183.02 6277.29,6183.02 ; 3709.22,3943.02 3842.91,3943.02 3842.75,4023.02 3709.22,4023.02 3709.22,3943.02 ; 3709.22,5023.02 3842.91,5023.02 3842.75,5103.02 3709.22,5103.02 3709.22,5023.02 ; 3709.22,6103.02 3842.91,6103.02 3842.75,6183.02 3709.22,6183.02 3709.22,6103.02 ; 4106.07,3227.12 4106.07,3658.92 4186.07,3659.08 4186.07,3227.12 4106.07,3227.12 ; 4106.07,4307.12 4106.07,4738.92 4186.07,4739.08 4186.07,4307.12 4106.07,4307.12 ; 4106.07,5387.12 4106.07,5818.92 4186.07,5819.08 4186.07,5387.12 4106.07,5387.12 ; 4106.07,6467.12 4106.07,6898.92 4186.07,6899.08 4186.07,6467.12 4106.07,6467.12 ; 4449.22,3943.02 4582.91,3943.02 4582.75,4023.02 4449.22,4023.02 4449.22,3943.02 ; 4449.22,5023.02 4582.91,5023.02 4582.75,5103.02 4449.22,5103.02 4449.22,5023.02 ; 4449.22,6103.02 4582.91,6103.02 4582.75,6183.02 4449.22,6183.02 4449.22,6103.02 ; 4846.07,3227.12 4846.07,3658.92 4926.07,3659.08 4926.07,3227.12 4846.07,3227.12 ; 4846.07,4307.12 4846.07,4738.92 4926.07,4739.08 4926.07,4307.12 4846.07,4307.12 ; 4846.07,5387.12 4846.07,5818.92 4926.07,5819.08 4926.07,5387.12 4846.07,5387.12 ; 4846.07,6467.12 4846.07,6898.92 4926.07,6899.08 4926.07,6467.12 4846.07,6467.12 ; 5189.22,3943.02 5322.91,3943.02 5322.75,4023.02 5189.22,4023.02 5189.22,3943.02 ; 5189.22,5023.02 5322.91,5023.02 5322.75,5103.02 5189.22,5103.02 5189.22,5023.02 ; 5189.22,6103.02 5322.91,6103.02 5322.75,6183.02 5189.22,6183.02 5189.22,6103.02 ; 5586.07,3227.12 5586.07,3658.92 5666.07,3659.08 5666.07,3227.12 5586.07,3227.12 ; 5586.07,4307.12 5586.07,4738.92 5666.07,4739.08 5666.07,4307.12 5586.07,4307.12 ; 5586.07,5387.12 5586.07,5818.92 5666.07,5819.08 5666.07,5387.12 5586.07,5387.12 ; 5586.07,6467.12 5586.07,6898.92 5666.07,6899.08 5666.07,6467.12 5586.07,6467.12 ; 5929.22,3943.02 6062.91,3943.02 6062.75,4023.02 5929.22,4023.02 5929.22,3943.02 ; 5929.22,5023.02 6062.91,5023.02 6062.75,5103.02 5929.22,5103.02 5929.22,5023.02 ; 5929.22,6103.02 6062.91,6103.02 6062.75,6183.02 5929.22,6183.02 5929.22,6103.02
